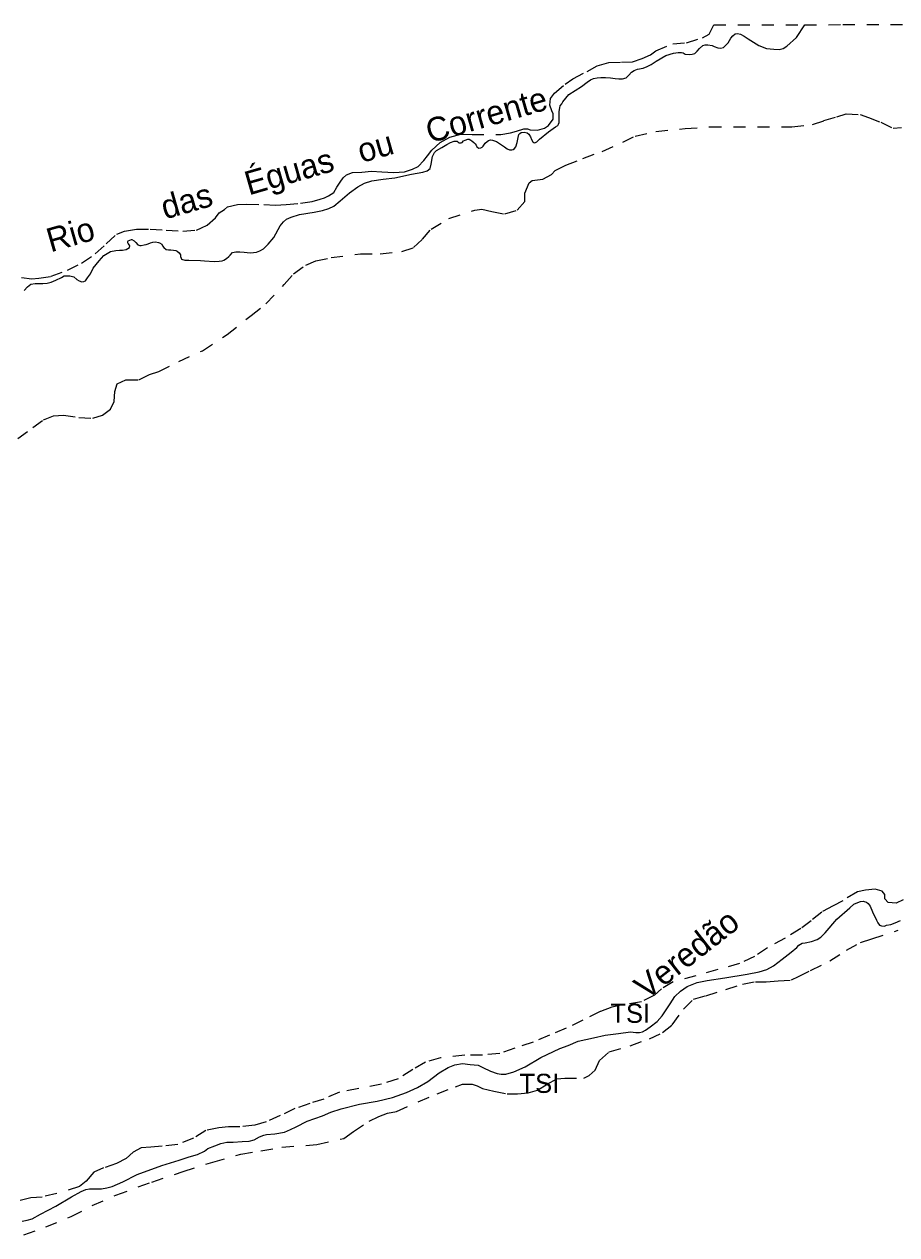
# Model space of a CAD drawing. Extents: x 391.8 to 446, y 8452 to 8507.5.
# Drawn here: x 431.31 to 438.61, y 8497.36 to 8507.48 of the extents above; entities that cross this region are included whole.
import ezdxf
from ezdxf.enums import TextEntityAlignment as Align

# ---------------------------------------------------------------- set-up
doc = ezdxf.new("R2010")
doc.units = 0
doc.header["$LTSCALE"] = 0.064
doc.linetypes.add('SHORT_DASHED', pattern=[2.7, 1.5, -1.2])
for name, color, linetype, lineweight in [('21', 7, 'SHORT_DASHED', 13), ('62', 7, 'SHORT_DASHED', 13), ('7', 7, 'Continuous', 25)]:
    doc.layers.add(name, color=color, linetype=linetype, lineweight=lineweight)
doc.layers.add('61', color=7, linetype='Continuous')

msp = doc.modelspace()

# ---------------------------------------------------------------- linework, layer by layer
at = {"layer": '21'}
for points in [[(436.9821, 8507.3698), (437.0397, 8507.4022), (437.0788, 8507.4782)], [(431.2879, 8505.3638), (431.3728, 8505.3528), (431.4318, 8505.3602), (431.5352, 8505.3749), (431.6718, 8505.4265), (431.79, 8505.4855), (431.9044, 8505.563), (431.9967, 8505.6478), (432.0833, 8505.7283), (432.1498, 8505.7541), (432.2495, 8505.7688), (432.3639, 8505.7688), (432.4968, 8505.7615), (432.6371, 8505.7541), (432.7516, 8505.7615), (432.7922, 8505.7799), (432.8402, 8505.802), (432.9103, 8505.8647), (432.9399, 8505.9053), (432.9842, 8505.9348), (433.01, 8505.9569), (433.0949, 8505.9753), (433.1725, 8505.979), (433.3128, 8505.9753), (433.411, 8505.9691), (433.4996, 8505.9765), (433.6214, 8505.9876), (433.7174, 8506.0023), (433.7839, 8506.0208), (433.8221, 8506.0329), (433.8554, 8506.0477), (433.8997, 8506.0772), (433.9255, 8506.1214), (433.9514, 8506.162), (433.9772, 8506.1989), (434.0067, 8506.2247), (434.0547, 8506.2431), (434.1323, 8506.2468), (434.2135, 8506.2542), (434.3021, 8506.2505), (434.4018, 8506.2431), (434.4904, 8506.2505), (434.5568, 8506.2726), (434.6048, 8506.2947), (434.6528, 8506.3427), (434.6824, 8506.3832), (434.7193, 8506.4312), (434.7894, 8506.4938), (434.8707, 8506.5381), (434.963, 8506.5639), (435.0553, 8506.5602), (435.2952, 8506.5602), (435.3765, 8506.575), (435.4281, 8506.5897), (435.4872, 8506.6081), (435.5204, 8506.6081), (435.5426, 8506.6008), (435.6017, 8506.5971), (435.6607, 8506.6155), (435.694, 8506.6376), (435.7346, 8506.6893), (435.7346, 8506.7335), (435.7235, 8506.7593), (435.705, 8506.8072), (435.7124, 8506.8625), (435.7457, 8506.9068), (435.8329, 8506.9823), (435.8993, 8507.0266), (436.0175, 8507.0893), (436.1024, 8507.1372), (436.1984, 8507.163), (436.3055, 8507.1667), (436.3978, 8507.1704), (436.479, 8507.1962), (436.5491, 8507.2294), (436.5934, 8507.2626), (436.7337, 8507.3215), (436.8482, 8507.3289), (436.9821, 8507.3698)], [(437.7307, 8506.6252), (437.9016, 8506.6456), (437.998, 8506.6777), (438.1073, 8506.7098), (438.1845, 8506.7354), (438.3002, 8506.729), (438.3709, 8506.7033), (438.4737, 8506.6648), (438.5766, 8506.6135), (438.6473, 8506.6199)], [(436.1429, 8506.4197), (436.3165, 8506.4968), (436.4194, 8506.5481), (436.5929, 8506.5866), (436.8372, 8506.6123), (437.0429, 8506.6252), (437.7307, 8506.6252)], [(431.257, 8504.018), (431.3811, 8504.1102), (431.4711, 8504.1744), (431.5546, 8504.2065), (431.6382, 8504.2129), (431.7668, 8504.1936), (431.8825, 8504.1872), (431.9661, 8504.2129), (432.0303, 8504.2642), (432.0625, 8504.3284), (432.0689, 8504.4119), (432.0882, 8504.4761), (432.1589, 8504.5082), (432.2682, 8504.5082), (432.3582, 8504.5531), (432.4353, 8504.5788), (432.6025, 8504.6623), (432.8017, 8504.7522), (433.0075, 8504.887), (433.2067, 8505.0475), (433.3305, 8505.1461), (433.4847, 8505.3066), (433.5619, 8505.3965), (433.6647, 8505.4671), (433.7483, 8505.5056), (433.8769, 8505.5313), (434.1212, 8505.5634), (434.2883, 8505.5634), (434.4683, 8505.5826), (434.5647, 8505.6147), (434.6418, 8505.6854), (434.7126, 8505.7688), (434.8604, 8505.8587), (435.079, 8505.9293), (435.1368, 8505.9357), (435.2204, 8505.9165), (435.3297, 8505.8972), (435.4325, 8505.9293), (435.4968, 8505.9999), (435.4968, 8506.0706), (435.5323, 8506.1565), (435.558, 8506.1758), (435.648, 8506.1886), (435.7187, 8506.2271), (435.7508, 8506.2592), (435.8408, 8506.3042), (435.9822, 8506.3619), (436.1429, 8506.4197)], [(438.6603, 8500.1581), (438.6018, 8500.1289), (438.5361, 8500.1362), (438.5068, 8500.1654), (438.5068, 8500.2019), (438.4849, 8500.2311), (438.4264, 8500.2457), (438.346, 8500.2384), (438.2802, 8500.2238), (438.156, 8500.1508), (438.0756, 8500.107), (437.9806, 8500.0559)], [(437.9806, 8500.0559), (437.8929, 8499.9829), (437.8052, 8499.9172), (437.6736, 8499.8369), (437.5274, 8499.7566), (437.4178, 8499.6836), (437.2936, 8499.6253)], [(434.2764, 8498.3435), (434.3495, 8498.3727), (434.4226, 8498.3873), (434.7633, 8498.5357), (434.9168, 8498.5941), (434.9752, 8498.616), (435.0556, 8498.616), (435.0995, 8498.6014), (435.1433, 8498.5795), (435.2384, 8498.5576), (435.348, 8498.5357), (435.4357, 8498.5357), (435.5234, 8498.543), (435.6038, 8498.5649), (435.6842, 8498.616), (435.7646, 8498.6597), (435.8304, 8498.667), (435.9912, 8498.667), (436.035, 8498.6889), (436.0862, 8498.7327), (436.1227, 8498.813), (436.2031, 8498.886), (436.3785, 8498.9371), (436.5393, 8498.9955), (436.649, 8499.0466), (436.7294, 8499.1123), (436.8244, 8499.2437), (436.908, 8499.3267), (437.0103, 8499.3559), (437.1784, 8499.407), (437.3173, 8499.4508), (437.4269, 8499.4726), (437.5146, 8499.4726), (437.6169, 8499.4799), (437.7266, 8499.4872), (437.785, 8499.5164), (437.8874, 8499.5675), (438.0482, 8499.6478), (438.187, 8499.7354), (438.304, 8499.8011), (438.399, 8499.8303), (438.6182, 8499.9033)], [(437.2936, 8499.6253), (437.1108, 8499.5742), (436.9281, 8499.5231), (436.7381, 8499.472), (436.6399, 8499.4125), (436.5814, 8499.3614), (436.4718, 8499.303), (436.3256, 8499.2811), (436.2233, 8499.2592), (436.1282, 8499.2227), (435.9821, 8499.1497), (435.8432, 8499.084), (435.7043, 8499.0256), (435.5655, 8498.9672), (435.412, 8498.9161), (435.2877, 8498.8723), (435.1416, 8498.8577), (434.9954, 8498.8577), (434.7907, 8498.8358), (434.6665, 8498.7993), (434.5608, 8498.7391), (434.4365, 8498.6588), (434.2977, 8498.615), (434.1076, 8498.5785), (433.9469, 8498.5493), (433.8153, 8498.491), (433.6984, 8498.4545), (433.5741, 8498.4107), (433.4499, 8498.3523), (433.3329, 8498.3012), (433.2379, 8498.272), (433.1136, 8498.2574), (433.0186, 8498.2574), (432.9382, 8498.2501), (432.8286, 8498.2282), (432.7263, 8498.1625), (432.5947, 8498.1114), (432.4632, 8498.0968), (432.3681, 8498.0895), (432.2877, 8498.0822), (432.222, 8498.0457), (432.1635, 8497.9946), (432.0831, 8497.9508), (431.9735, 8497.9143), (431.8931, 8497.8778), (431.8273, 8497.8048), (431.7735, 8497.7583), (431.5835, 8497.6999), (431.4592, 8497.6707), (431.3642, 8497.6634), (431.2765, 8497.6415)], [(433.2898, 8498.0588), (433.4652, 8498.088), (433.7575, 8498.1099), (433.9841, 8498.161), (434.0645, 8498.2194), (434.1961, 8498.307), (434.2764, 8498.3435)], [(431.3073, 8497.3551), (431.49, 8497.4208), (431.702, 8497.5084), (431.8792, 8497.599), (432.0765, 8497.6866), (432.3762, 8497.7961), (432.6393, 8497.8837), (432.8878, 8497.9639), (433.1217, 8498.0296), (433.2898, 8498.0588)]]:
    msp.add_lwpolyline(points, dxfattribs=at)
at = {"layer": '62'}
msp.add_line((437.0788, 8507.4782), (437.8375, 8507.48), dxfattribs=at)
msp.add_lwpolyline([(437.8375, 8507.48), (438.1565, 8507.4807), (439.2608, 8507.4832), (439.7828, 8507.4844)], dxfattribs=at)
at = {"layer": '7'}
for points in [[(436.675, 8507.2229), (436.7416, 8507.2419), (436.7796, 8507.249), (436.8058, 8507.249), (436.8224, 8507.2443), (436.8391, 8507.2348), (436.87, 8507.23), (436.8961, 8507.2324), (436.9176, 8507.2395), (436.939, 8507.2585), (436.958, 8507.2799), (436.9865, 8507.306), (437.0055, 8507.3132), (437.0269, 8507.3132), (437.0626, 8507.306), (437.0816, 8507.2989), (437.1102, 8507.287), (437.134, 8507.2847), (437.1577, 8507.2894), (437.172, 8507.3037), (437.1982, 8507.3298), (437.2196, 8507.3678), (437.2362, 8507.3868), (437.2552, 8507.4034), (437.2743, 8507.4058), (437.3004, 8507.401), (437.3313, 8507.3844), (437.3646, 8507.3607), (437.4526, 8507.306), (437.5181, 8507.2825), (437.5799, 8507.2753), (437.6227, 8507.273), (437.6584, 8507.2825), (437.6893, 8507.3015), (437.7702, 8507.3727), (437.8375, 8507.48)], [(436.412, 8507.0963), (436.4382, 8507.1082), (436.4857, 8507.1177), (436.519, 8507.1295), (436.5523, 8507.1462), (436.5951, 8507.1747), (436.675, 8507.2229)], [(433.8054, 8505.925), (433.8577, 8505.9416), (433.9005, 8505.963), (433.9528, 8506.0057), (434.0313, 8506.0746), (434.1003, 8506.1245), (434.1573, 8506.1554), (434.2168, 8506.1744), (434.3119, 8506.1886), (434.4094, 8506.1981), (434.5497, 8506.229), (434.6433, 8506.2466), (434.6814, 8506.2584), (434.7051, 8506.2774), (434.7146, 8506.3131), (434.7242, 8506.3772), (434.7408, 8506.4104), (434.7575, 8506.4271), (434.8026, 8506.4532), (434.8454, 8506.4793), (434.8764, 8506.4959), (434.9049, 8506.5054), (434.9311, 8506.5054), (434.9382, 8506.4983), (434.9477, 8506.4912), (434.9643, 8506.4912), (434.9739, 8506.4959), (434.9834, 8506.5078), (434.9976, 8506.5149), (435.0214, 8506.5221), (435.0309, 8506.5221), (435.0452, 8506.5149), (435.0547, 8506.5078), (435.0714, 8506.4959), (435.0809, 8506.4841), (435.0904, 8506.4722), (435.0951, 8506.4579), (435.1118, 8506.4484), (435.1284, 8506.4508), (435.1403, 8506.4556), (435.1475, 8506.4651), (435.1665, 8506.4888), (435.1808, 8506.5031), (435.1926, 8506.5126), (435.2093, 8506.5173), (435.2259, 8506.5149), (435.2592, 8506.5031), (435.3274, 8506.4585), (435.3488, 8506.4418), (435.3678, 8506.4323), (435.3892, 8506.4323), (435.3987, 8506.4371), (435.4106, 8506.4442), (435.4225, 8506.4585), (435.432, 8506.4941), (435.4415, 8506.5368), (435.4463, 8506.5606), (435.4558, 8506.5701), (435.4653, 8506.5772), (435.4914, 8506.582), (435.5176, 8506.5748), (435.5295, 8506.5653), (435.5438, 8506.5416), (435.5533, 8506.5202), (435.5628, 8506.5012), (435.5723, 8506.4941), (435.5818, 8506.4917), (435.5961, 8506.5012), (435.6199, 8506.5226), (435.6936, 8506.5843), (435.753, 8506.6247), (435.7721, 8506.6366), (435.7792, 8506.6485), (435.7839, 8506.6627), (435.7839, 8506.753), (435.7887, 8506.7838), (435.7935, 8506.8028), (435.8077, 8506.8195), (435.8149, 8506.8361), (435.8651, 8506.8968), (435.9721, 8506.9633), (436.0173, 8506.9989), (436.0458, 8507.0203), (436.072, 8507.0298), (436.1029, 8507.0369), (436.1314, 8507.0393), (436.1718, 8507.0393), (436.2123, 8507.0345), (436.2527, 8507.0298), (436.2836, 8507.0274), (436.3145, 8507.0274), (436.3454, 8507.0369), (436.3668, 8507.0583), (436.3882, 8507.082), (436.412, 8507.0963)], [(433.4503, 8505.7961), (433.4788, 8505.8318), (433.5026, 8505.8531), (433.543, 8505.8698), (433.612, 8505.8911), (433.7341, 8505.9107), (433.8054, 8505.925)], [(431.3092, 8505.2574), (431.3384, 8505.2875), (431.3503, 8505.2993), (431.3646, 8505.3088), (431.4026, 8505.316), (431.4336, 8505.316), (431.4645, 8505.3136), (431.5025, 8505.3183), (431.5358, 8505.3255), (431.5739, 8505.3421), (431.6214, 8505.3658), (431.6428, 8505.3777), (431.6642, 8505.3801), (431.6904, 8505.3777), (431.7237, 8505.3706), (431.7498, 8505.3492), (431.7689, 8505.3373), (431.7926, 8505.3278), (431.8093, 8505.3302), (431.8236, 8505.3373), (431.8402, 8505.3611), (431.864, 8505.3967), (431.8878, 8505.4442), (431.9377, 8505.5036), (431.9758, 8505.5487), (432.0305, 8505.582), (432.0756, 8505.5915), (432.1066, 8505.5938), (432.1327, 8505.5938), (432.1636, 8505.5986), (432.1898, 8505.6152), (432.1922, 8505.6295), (432.1898, 8505.6366), (432.1803, 8505.6485), (432.1755, 8505.6556), (432.1755, 8505.6651), (432.1803, 8505.6722), (432.2064, 8505.6817), (432.2112, 8505.6817), (432.2302, 8505.6722), (432.2445, 8505.658), (432.2611, 8505.639), (432.2766, 8505.6324), (432.2885, 8505.6324), (432.3123, 8505.6371), (432.329, 8505.6419), (432.3456, 8505.6466), (432.367, 8505.6561), (432.386, 8505.6609), (432.4074, 8505.6632), (432.4336, 8505.6585), (432.4407, 8505.6561), (432.4598, 8505.6442), (432.4669, 8505.63), (432.4788, 8505.6157), (432.4978, 8505.5991), (432.5168, 8505.5967), (432.5359, 8505.5967), (432.5596, 8505.5944), (432.5787, 8505.5896), (432.5905, 8505.5849), (432.6048, 8505.5706), (432.6167, 8505.554), (432.6167, 8505.5397), (432.6215, 8505.5255), (432.6262, 8505.5184), (432.6524, 8505.5112), (432.6881, 8505.5089), (432.7832, 8505.5065), (432.8165, 8505.5041), (432.8973, 8505.4994), (432.9401, 8505.5017), (432.9663, 8505.5041), (432.9806, 8505.5112), (433.002, 8505.5231), (433.021, 8505.5397), (433.0329, 8505.5516), (433.0519, 8505.573), (433.0804, 8505.5801), (433.1137, 8505.5801), (433.1494, 8505.5777), (433.2006, 8505.5705), (433.2267, 8505.5753), (433.2529, 8505.5776), (433.2814, 8505.5871), (433.3123, 8505.6038), (433.3504, 8505.6441), (433.3979, 8505.7011), (433.4503, 8505.7961)], [(433.4067, 8498.2009), (433.4879, 8498.2125), (433.5382, 8498.2357), (433.5846, 8498.2588), (433.6774, 8498.3052), (433.805, 8498.3515), (433.8746, 8498.3824), (433.9597, 8498.4095), (434.1144, 8498.4481), (434.2627, 8498.4719), (434.3903, 8498.5028), (434.5064, 8498.5453), (434.5992, 8498.5878), (434.6843, 8498.638), (434.781, 8498.7114), (434.8544, 8498.7539), (434.9125, 8498.7771), (434.9743, 8498.7886), (435.0401, 8498.7809), (435.1058, 8498.7732), (435.1445, 8498.7539), (435.2102, 8498.723), (435.2644, 8498.7037), (435.2992, 8498.6998), (435.3379, 8498.6998), (435.4036, 8498.7191), (435.5003, 8498.7616), (435.6318, 8498.8389), (435.7885, 8498.9128), (435.8581, 8498.9399), (435.9432, 8498.9746), (436.0708, 8499.0017), (436.1675, 8499.0248), (436.2796, 8499.0403), (436.3802, 8499.0519), (436.4239, 8499.0467), (436.4566, 8499.0485), (436.4802, 8499.054), (436.5074, 8499.0667), (436.5456, 8499.0957), (436.6037, 8499.141), (436.6454, 8499.1882), (436.7126, 8499.2879), (436.7525, 8499.3477), (436.7998, 8499.3949), (436.8542, 8499.433), (436.9378, 8499.4674), (437.0213, 8499.4819), (437.1693, 8499.5064), (437.3563, 8499.5354), (437.4562, 8499.5553), (437.5216, 8499.5735), (437.576, 8499.6061), (437.6487, 8499.6623), (437.7249, 8499.7185), (437.7721, 8499.7584), (437.7885, 8499.7784), (437.8157, 8499.7947), (437.8411, 8499.7983), (437.8932, 8499.8105), (437.9422, 8499.8268), (437.9731, 8499.8449), (438.0094, 8499.8812), (438.1074, 8499.9972), (438.2164, 8500.0915), (438.2491, 8500.1205), (438.2817, 8500.135), (438.3053, 8500.1441), (438.3253, 8500.1459), (438.3362, 8500.1441), (438.3544, 8500.1387), (438.3689, 8500.1278), (438.3852, 8500.1042), (438.4052, 8500.0571), (438.4379, 8499.9882), (438.4488, 8499.9646), (438.4633, 8499.9465), (438.4797, 8499.9392), (438.5051, 8499.9374), (438.5214, 8499.9446), (438.5577, 8499.9501), (438.594, 8499.9664), (438.6394, 8499.9845)], [(433.1321, 8498.1352), (433.1901, 8498.1391), (433.2326, 8498.1507), (433.2791, 8498.1739), (433.3139, 8498.1893), (433.3371, 8498.1932), (433.4067, 8498.2009)], [(431.2918, 8497.4683), (431.3344, 8497.4761), (431.3769, 8497.4876), (431.4465, 8497.5263), (431.5741, 8497.5958), (431.7056, 8497.673), (431.7853, 8497.7173), (431.824, 8497.7328), (431.8549, 8497.7405), (431.9555, 8497.7405), (432.0019, 8497.7482), (432.0444, 8497.7598), (432.1334, 8497.7984), (432.2533, 8497.8602), (432.4621, 8497.9336), (432.6052, 8497.98), (432.6903, 8498.007), (432.7599, 8498.0263), (432.8179, 8498.0534), (432.845, 8498.0765), (432.903, 8498.0997), (432.9533, 8498.119), (433.0035, 8498.1306), (433.0577, 8498.1306), (433.1321, 8498.1352)]]:
    msp.add_lwpolyline(points, dxfattribs=at)

# ---------------------------------------------------------------- texts
at = {"layer": '61'}
for s, rotation, p in [('Rio        das    Éguas   ou    Corrente', 16.043, (433.6169, 8506.1746)), ("Veredão                                                  ou            Ponta                                         d' Água", 38.012, (440.6725, 8502.5665))]:
    msp.add_text(s, height=0.2, rotation=rotation, dxfattribs=at).set_placement(p, align=Align.CENTER)
for p in [(436.3786, 8499.1286), (435.6187, 8498.5422)]:
    msp.add_text('TSI', height=0.16, dxfattribs=at).set_placement(p, align=Align.CENTER)

doc.saveas('drawing.dxf')
